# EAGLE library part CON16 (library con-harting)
CONNECTOR
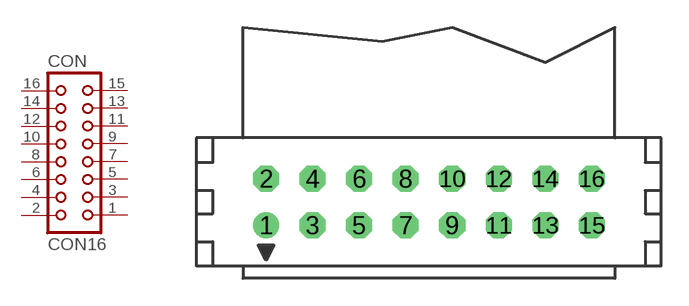
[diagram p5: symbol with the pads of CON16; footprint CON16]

Designator prefix CON

## CON16 (OC_FARNELL: unknown; OC_NEWARK: unknown)  [CON16]
1  1  pas
2  2  pas
3  3  pas
4  4  pas
5  5  pas
6  6  pas
7  7  pas
8  8  pas
9  9  pas
10  10  pas
11  11  pas
12  12  pas
13  13  pas
14  14  pas
15  15  pas
16  16  pas

## Footprint CON16 (pad centres in mm)
CONNECTOR
drill 0.914 round: 1 -8.89,-1.27
drill 0.914 octagon: 2 -8.89,1.27; 3 -6.35,-1.27; 4 -6.35,1.27; 5 -3.81,-1.27; 6 -3.81,1.27; 7 -1.27,-1.27; 8 -1.27,1.27; 9 1.27,-1.27; 10 1.27,1.27; 11 3.81,-1.27; 12 3.81,1.27; 13 6.35,-1.27; 14 6.35,1.27; 15 8.89,-1.27; 16 8.89,1.27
